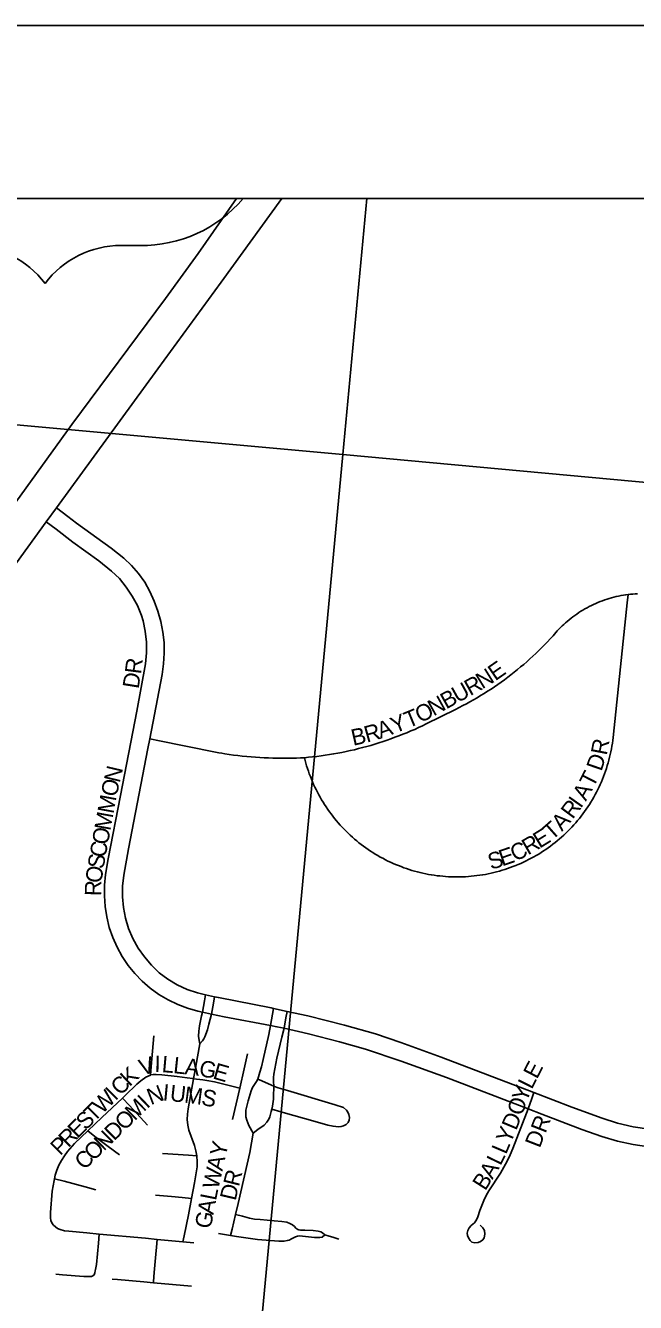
# Model space of a CAD drawing. Extents: x -209 to 4852, y 0 to 905.
# Drawn here: x 110.88 to 117.93, y 325.8 to 340.56 of the extents above; entities that cross this region are included whole.
import ezdxf

# ---------------------------------------------------------------- set-up
doc = ezdxf.new("R2010")
doc.units = 0
for name, color, linetype in [('Default', 7, 'Continuous'), ('GM_X_Airport_Location_Class_2', 7, 'Continuous'), ('GM_X_Airport_Location_Class_3', 7, 'Continuous'), ('GM_X_Interchange_Ramps', 7, 'Continuous'), ('GM_X_Minor_Lake_Text', 7, 'Continuous'), ('GM_X_Minor_River', 7, 'Continuous'), ('GM_X_US_Location', 7, 'Continuous'), ('GM_X_US_Route', 7, 'Continuous'), ('SH_Data', 7, 'Continuous')]:
    doc.layers.add(name, color=color, linetype=linetype)

msp = doc.modelspace()

# ---------------------------------------------------------------- linework, layer by layer
at = {"layer": 'Default'}
for points in [[(59.342, 338.559), (195.342, 338.559), (195.342, 202.559), (59.342, 202.559)], [(195.342, 202.559), (195.342, 338.559), (59.342, 338.559), (59.342, 202.559)]]:
    msp.add_lwpolyline(points, close=True, dxfattribs=at)
at = {"layer": 'GM_X_Airport_Location_Class_2'}
for points in [[(111.234, 334.986), (112.407, 336.59), (113.139, 337.594), (113.838, 338.559)], [(111.116, 334.823), (111.234, 334.986)], [(111.234, 334.986), (111.366, 334.885), (111.465, 334.809), (111.868, 334.518), (112.013, 334.402), (112.102, 334.317), (112.183, 334.225), (112.255, 334.125), (112.314, 334.017), (112.364, 333.904), (112.405, 333.788), (112.44, 333.669), (112.464, 333.549), (112.477, 333.426), (112.479, 333.303), (112.47, 333.18), (112.454, 333.057), (112.312, 332.314)], [(100.635, 320.765), (100.879, 321.1), (101.138, 321.454), (101.471, 321.891), (101.832, 322.33), (102.235, 322.799), (102.722, 323.368), (103.032, 323.752), (103.379, 324.196), (103.741, 324.686), (105.127, 326.6), (106.118, 327.963), (107.027, 329.212), (108.315, 330.965), (109.157, 332.119), (109.921, 333.176), (111.116, 334.823)], [(111.116, 334.823), (111.229, 334.736), (111.422, 334.587), (111.725, 334.37), (111.871, 334.253), (111.961, 334.166), (112.041, 334.069), (112.11, 333.965), (112.17, 333.855), (112.218, 333.739), (112.236, 333.679), (112.261, 333.557), (112.275, 333.432), (112.276, 333.307), (112.264, 333.183), (112.162, 332.633), (111.974, 331.658), (111.831, 330.928), (111.802, 330.745), (111.79, 330.622), (111.788, 330.499), (111.796, 330.376), (111.815, 330.255), (111.845, 330.135), (111.886, 330.019), (111.936, 329.907), (111.995, 329.799), (112.063, 329.696), (112.14, 329.6), (112.225, 329.512), (112.318, 329.431), (112.419, 329.36), (112.525, 329.298), (112.635, 329.244), (112.75, 329.2), (112.869, 329.166), (112.921, 329.155)], [(114.099, 332.096), (114.147, 332.101), (114.194, 332.106), (114.243, 332.111), (114.292, 332.118), (114.34, 332.125), (114.389, 332.132), (114.437, 332.14), (114.485, 332.149), (114.533, 332.158), (114.582, 332.168), (114.63, 332.178), (114.677, 332.189), (114.725, 332.201), (114.772, 332.213), (114.82, 332.226), (114.867, 332.239), (114.914, 332.253), (114.961, 332.268), (115.008, 332.283), (115.054, 332.299), (115.1, 332.315), (115.146, 332.332), (115.192, 332.349), (115.238, 332.367), (115.283, 332.385), (115.329, 332.405), (115.374, 332.424), (115.418, 332.444), (115.463, 332.465), (115.507, 332.486), (115.845, 332.655), (115.887, 332.676), (115.929, 332.698), (115.971, 332.72), (116.013, 332.743), (116.054, 332.766), (116.095, 332.79), (116.136, 332.814), (116.176, 332.839), (116.216, 332.864), (116.256, 332.89), (116.295, 332.916), (116.334, 332.943), (116.373, 332.97), (116.412, 332.998), (116.45, 333.027), (116.487, 333.055), (116.524, 333.085), (116.561, 333.114), (116.598, 333.145), (116.634, 333.175), (116.67, 333.206), (116.705, 333.238), (116.74, 333.27), (116.775, 333.302), (116.809, 333.335), (116.842, 333.369), (116.876, 333.402), (116.909, 333.437), (116.941, 333.471), (116.973, 333.506), (117.005, 333.542), (117.022, 333.561), (117.041, 333.581), (117.059, 333.6), (117.078, 333.619), (117.098, 333.637), (117.118, 333.655), (117.138, 333.672), (117.159, 333.69), (117.181, 333.708), (117.203, 333.725), (117.225, 333.741), (117.248, 333.757), (117.271, 333.773), (117.295, 333.788), (117.318, 333.803), (117.342, 333.817), (117.367, 333.83), (117.391, 333.843), (117.416, 333.856), (117.441, 333.868), (117.467, 333.88), (117.492, 333.891), (117.518, 333.901), (117.544, 333.911), (117.57, 333.92), (117.597, 333.929), (117.623, 333.938), (117.65, 333.945), (117.677, 333.952), (117.704, 333.959), (117.731, 333.965), (117.759, 333.971), (117.786, 333.975), (117.814, 333.98), (117.841, 333.984)], [(114.099, 332.096), (114.107, 332.065), (114.116, 332.034), (114.125, 332.003), (114.135, 331.972), (114.145, 331.941), (114.156, 331.909), (114.168, 331.878), (114.18, 331.848), (114.193, 331.817), (114.206, 331.787), (114.22, 331.757), (114.235, 331.727), (114.25, 331.698), (114.265, 331.668), (114.281, 331.639), (114.298, 331.611), (114.315, 331.583), (114.332, 331.554), (114.35, 331.527), (114.369, 331.499), (114.388, 331.472), (114.408, 331.446), (114.428, 331.42), (114.448, 331.394), (114.469, 331.368), (114.491, 331.343), (114.513, 331.318), (114.535, 331.294), (114.558, 331.27), (114.581, 331.246), (114.605, 331.223), (114.629, 331.2), (114.654, 331.178), (114.678, 331.156), (114.704, 331.135), (114.729, 331.114), (114.755, 331.094), (114.782, 331.074), (114.809, 331.055), (114.836, 331.036), (114.863, 331.017), (114.891, 330.999), (114.919, 330.982), (114.948, 330.965), (114.976, 330.948), (115.005, 330.933), (115.035, 330.917), (115.064, 330.902), (115.094, 330.888), (115.124, 330.874), (115.154, 330.861), (115.185, 330.849), (115.216, 330.837), (115.247, 330.825), (115.278, 330.814), (115.31, 330.804), (115.341, 330.794), (115.373, 330.785), (115.405, 330.776), (115.437, 330.768), (115.469, 330.761), (115.502, 330.754), (115.534, 330.748), (115.567, 330.742), (115.599, 330.737), (115.632, 330.732), (115.665, 330.729), (115.698, 330.725), (115.731, 330.723), (115.764, 330.72), (115.797, 330.719), (115.83, 330.718), (115.863, 330.718), (115.896, 330.718), (115.929, 330.719), (115.962, 330.72), (115.995, 330.723), (116.028, 330.725), (116.061, 330.729), (116.094, 330.733), (116.127, 330.737), (116.159, 330.742), (116.192, 330.748), (116.224, 330.754), (116.257, 330.761), (116.289, 330.769), (116.321, 330.777), (116.353, 330.785), (116.385, 330.795), (116.416, 330.804), (116.448, 330.815), (116.479, 330.826), (116.51, 330.837), (116.541, 330.849), (116.552, 330.854), (116.571, 330.862), (116.602, 330.875), (116.632, 330.889), (116.662, 330.903), (116.691, 330.918), (116.721, 330.933), (116.75, 330.949), (116.778, 330.966), (116.807, 330.983), (116.835, 331), (116.863, 331.018), (116.89, 331.036), (116.917, 331.055), (116.944, 331.075), (116.97, 331.095), (116.996, 331.115), (117.022, 331.136), (117.047, 331.157), (117.072, 331.179), (117.097, 331.201), (117.121, 331.224), (117.144, 331.247), (117.168, 331.271), (117.19, 331.295), (117.213, 331.319), (117.235, 331.344), (117.256, 331.369), (117.277, 331.395), (117.298, 331.421), (117.318, 331.447), (117.337, 331.474), (117.356, 331.501), (117.375, 331.528), (117.393, 331.556), (117.411, 331.584), (117.428, 331.612), (117.444, 331.641), (117.46, 331.67), (117.476, 331.699), (117.491, 331.728), (117.505, 331.758), (117.519, 331.788), (117.532, 331.819), (117.545, 331.849), (117.557, 331.88), (117.569, 331.911), (117.58, 331.942), (117.59, 331.973), (117.6, 332.005), (117.61, 332.037), (117.618, 332.068), (117.627, 332.101), (117.634, 332.133), (117.641, 332.165), (117.648, 332.197), (117.654, 332.23), (117.659, 332.263), (117.663, 332.296), (117.668, 332.328), (117.804, 333.628), (117.831, 333.887), (117.841, 333.984)], [(117.841, 333.984), (117.868, 333.986), (117.894, 333.988), (117.921, 333.99), (117.948, 333.99)], [(112.312, 332.314), (112.291, 332.203), (112.066, 331.044), (112.011, 330.738), (111.998, 330.613), (111.996, 330.488), (112.007, 330.363), (112.03, 330.24), (112.067, 330.12), (112.116, 330.005), (112.178, 329.896), (112.25, 329.793), (112.331, 329.697), (112.422, 329.611), (112.523, 329.536), (112.63, 329.472), (112.744, 329.418), (112.863, 329.378), (112.958, 329.356)], [(112.312, 332.314), (112.333, 332.31), (112.404, 332.295), (113.073, 332.159), (113.109, 332.153), (113.145, 332.147), (113.181, 332.141), (113.231, 332.134), (113.281, 332.127), (113.332, 332.121), (113.382, 332.115), (113.433, 332.11), (113.483, 332.105), (113.534, 332.101), (113.584, 332.098), (113.635, 332.095), (113.686, 332.093), (113.736, 332.091), (113.787, 332.09), (113.832, 332.089), (113.876, 332.089), (113.921, 332.09), (113.965, 332.091), (114.01, 332.092), (114.054, 332.094), (114.099, 332.096)], [(112.921, 329.155), (112.945, 329.287), (112.958, 329.356)], [(112.958, 329.356), (113.062, 329.333)], [(113.024, 329.133), (113.048, 329.258), (113.062, 329.333)], [(113.062, 329.333), (113.106, 329.323), (113.715, 329.203), (113.741, 329.198)], [(112.89, 328.79), (112.882, 328.826), (112.875, 328.876), (112.879, 328.937), (112.886, 328.998), (112.909, 329.112), (112.921, 329.155)], [(112.921, 329.155), (113.024, 329.133)], [(113.708, 329.001), (113.731, 329.133), (113.741, 329.198)], [(113.741, 329.198), (113.899, 329.164)], [(113.899, 329.164), (113.886, 329.088), (113.865, 328.968)], [(113.899, 329.164), (114.14, 329.112), (114.562, 329.006), (114.92, 328.904), (115.214, 328.805), (115.68, 328.634), (116.751, 328.225)], [(112.89, 328.79), (112.923, 328.825), (112.936, 328.846), (112.949, 328.871), (112.979, 328.952), (112.995, 329.018), (113.024, 329.133)], [(113.024, 329.133), (113.171, 329.101), (113.708, 329.001)], [(113.56, 328.38), (113.57, 328.408), (113.586, 328.46), (113.605, 328.524), (113.622, 328.608), (113.687, 328.896), (113.708, 329.001)], [(113.708, 329.001), (113.781, 328.987), (113.865, 328.968)], [(112.321, 328.428), (112.33, 328.525), (112.36, 328.88)], [(113.865, 328.968), (113.84, 328.864), (113.782, 328.622), (113.745, 328.437), (113.741, 328.398), (113.742, 328.353), (113.746, 328.298)], [(113.865, 328.968), (114.145, 328.906), (114.506, 328.812), (114.804, 328.726), (115.216, 328.59), (115.741, 328.398), (116.684, 328.038)], [(112.819, 328.386), (112.845, 328.529), (112.89, 328.79)], [(113.353, 328.277), (113.404, 328.498), (113.44, 328.674)], [(111.998, 328.161), (112.029, 328.19), (112.161, 328.321), (112.209, 328.361), (112.265, 328.403), (112.293, 328.416), (112.321, 328.428)], [(112.321, 328.428), (112.326, 328.43), (112.354, 328.435), (112.388, 328.436), (112.452, 328.432), (112.63, 328.41), (112.743, 328.395), (112.81, 328.387), (112.819, 328.386)], [(112.856, 327.495), (112.845, 327.553), (112.829, 327.613), (112.764, 327.789), (112.751, 327.85), (112.745, 327.913), (112.747, 327.975), (112.755, 328.037), (112.819, 328.386)], [(112.819, 328.386), (112.924, 328.373), (112.97, 328.365), (113.061, 328.348), (113.321, 328.284), (113.353, 328.277)], [(113.27, 327.915), (113.353, 328.277)], [(113.509, 327.755), (113.458, 327.846), (113.434, 327.905), (113.423, 327.944), (113.421, 327.981), (113.424, 328.022), (113.435, 328.07), (113.45, 328.129), (113.484, 328.247), (113.5, 328.285), (113.522, 328.318), (113.544, 328.353), (113.56, 328.38)], [(113.746, 328.298), (113.579, 328.371), (113.56, 328.38)], [(113.746, 328.298), (113.745, 328.272), (113.744, 328.204), (113.741, 328.148), (113.731, 328.067), (113.723, 328.033)], [(113.723, 328.033), (113.827, 328.003), (114.249, 327.884), (114.369, 327.849), (114.431, 327.836), (114.493, 327.831), (114.524, 327.835), (114.552, 327.841), (114.583, 327.857), (114.604, 327.879), (114.617, 327.907), (114.619, 327.938), (114.614, 327.971), (114.603, 327.999), (114.585, 328.024), (114.55, 328.052), (114.455, 328.084), (113.904, 328.249), (113.797, 328.279), (113.753, 328.295), (113.746, 328.298)], [(111.597, 327.782), (111.757, 327.936), (111.998, 328.161)], [(111.998, 328.161), (112.078, 328.077), (112.288, 327.85)], [(116.684, 328.038), (116.727, 328.158), (116.751, 328.225)], [(116.751, 328.225), (117.189, 328.058), (117.539, 327.928), (117.717, 327.872), (117.9, 327.831), (118.085, 327.804), (118.272, 327.79), (118.459, 327.789), (118.645, 327.802), (118.769, 327.82), (118.892, 327.846), (118.952, 327.864), (119.01, 327.887), (119.05, 327.908), (119.087, 327.932), (119.11, 327.946), (119.129, 327.954)], [(113.723, 328.033), (113.717, 328.007), (113.699, 327.946), (113.687, 327.919), (113.664, 327.882), (113.633, 327.849), (113.562, 327.797), (113.509, 327.755)], [(116.131, 326.691), (116.16, 326.663), (116.18, 326.632), (116.186, 326.589), (116.176, 326.548), (116.16, 326.524), (116.135, 326.503), (116.106, 326.491), (116.07, 326.487), (116.035, 326.497), (116.014, 326.517), (115.994, 326.546), (115.984, 326.573), (115.982, 326.601), (115.988, 326.632), (116.004, 326.663), (116.027, 326.689), (116.064, 326.72), (116.088, 326.753), (116.104, 326.788), (116.127, 326.861), (116.173, 326.978), (116.2, 327.035), (116.231, 327.089), (116.364, 327.295), (116.424, 327.399), (116.453, 327.456), (116.477, 327.506), (116.507, 327.579), (116.665, 327.988), (116.684, 328.038)], [(116.684, 328.038), (116.842, 327.977), (117.305, 327.8), (117.538, 327.716), (117.716, 327.664), (117.897, 327.626), (118.08, 327.6), (118.265, 327.587), (118.45, 327.59), (118.634, 327.608), (118.94, 327.662), (119.007, 327.671), (119.073, 327.676), (119.133, 327.677), (119.167, 327.679), (119.189, 327.681), (119.206, 327.684)], [(111.211, 327.23), (111.22, 327.269), (111.239, 327.328), (111.263, 327.385), (111.292, 327.44), (111.325, 327.493), (111.362, 327.543), (111.444, 327.636), (111.597, 327.782)], [(111.597, 327.782), (111.677, 327.719), (111.83, 327.601), (111.961, 327.507)], [(113.304, 326.818), (113.333, 326.942), (113.469, 327.531), (113.509, 327.755)], [(112.461, 327.521), (112.759, 327.502), (112.856, 327.495)], [(112.796, 327.002), (112.831, 327.181), (112.86, 327.367), (112.862, 327.429), (112.857, 327.491), (112.856, 327.495)], [(111.727, 326.59), (111.585, 326.603), (111.378, 326.623), (111.326, 326.628), (111.278, 326.642), (111.247, 326.656), (111.224, 326.672), (111.201, 326.692), (111.183, 326.714), (111.17, 326.747), (111.166, 326.777), (111.164, 326.839), (111.186, 327.086), (111.206, 327.209), (111.211, 327.23)], [(111.211, 327.23), (111.322, 327.2), (111.567, 327.134), (111.689, 327.101)], [(112.377, 327.04), (112.564, 327.026), (112.688, 327.013), (112.796, 327.002)], [(112.694, 326.501), (112.708, 326.568), (112.759, 326.813), (112.796, 327.002)], [(113.246, 326.572), (113.264, 326.647), (113.304, 326.818)], [(113.304, 326.818), (113.385, 326.795), (113.465, 326.775), (113.523, 326.763), (113.587, 326.758), (113.751, 326.744), (113.84, 326.734), (113.896, 326.726), (113.932, 326.713), (113.963, 326.698), (113.984, 326.677), (114.002, 326.657), (114.023, 326.644), (114.036, 326.64), (114.054, 326.636), (114.106, 326.636), (114.199, 326.63), (114.26, 326.623), (114.288, 326.617), (114.307, 326.606), (114.334, 326.58)], [(111.228, 326.125), (111.305, 326.119), (111.551, 326.1), (111.609, 326.099), (111.637, 326.101), (111.654, 326.107), (111.668, 326.12), (111.676, 326.141), (111.682, 326.165), (111.685, 326.179), (111.695, 326.24), (111.718, 326.483), (111.727, 326.59)], [(112.398, 326.528), (112.264, 326.541), (111.727, 326.59)], [(112.356, 326.027), (112.357, 326.043), (112.363, 326.146), (112.381, 326.356), (112.391, 326.437), (112.398, 326.528)], [(112.694, 326.501), (112.398, 326.528)], [(112.82, 326.49), (112.694, 326.501)], [(113.107, 326.598), (113.246, 326.572)], [(113.246, 326.572), (113.315, 326.56), (113.558, 326.528), (113.805, 326.508), (113.866, 326.508), (113.901, 326.514), (113.924, 326.521), (113.952, 326.535), (113.996, 326.558), (114.018, 326.567), (114.042, 326.569), (114.216, 326.55), (114.245, 326.549), (114.276, 326.549), (114.304, 326.556), (114.334, 326.58)], [(114.334, 326.58), (114.384, 326.565), (114.427, 326.553), (114.464, 326.542), (114.496, 326.531)], [(111.879, 326.07), (111.939, 326.064), (112.242, 326.038), (112.356, 326.027)], [(112.356, 326.027), (112.795, 325.986)]]:
    msp.add_lwpolyline(points, dxfattribs=at)
at = {"layer": 'GM_X_Interchange_Ramps'}
for p, q in [((113.39, 338.559), (108.813, 338.559)), ((111.981, 338.016), (112.2, 338.016))]:
    msp.add_line(p, q, dxfattribs=at)
for centre, radius, start, end in [((112.218, 339.554), 1.538, 269.3617, 319.6872), ((110.223, 336.918), 1.099, 36.8699, 90), ((111.981, 336.918), 1.099, 90, 143.1301)]:
    msp.add_arc(centre, radius, start, end, dxfattribs=at)
at = {"layer": 'GM_X_Minor_Lake_Text'}
msp.add_lwpolyline([(195.342, 338.559), (102.839, 338.559), (102.868, 338.282), (102.892, 337.606), (102.59, 336.588), (102.785, 335.735), (102.479, 335.255), (101.683, 335.242), (101.365, 334.52), (100.745, 334.207), (101.101, 332.393), (100.044, 332.219)], dxfattribs=at)
at = {"layer": 'GM_X_Minor_River'}
for points in [[(114.819, 338.559), (94.444, 338.559), (94.333, 337.437), (114.544, 335.599)], [(134.994, 338.559), (114.819, 338.559), (114.544, 335.599), (134.543, 333.757)], [(94.333, 337.437), (114.544, 335.599), (112.672, 315.623), (92.468, 317.445)], [(114.544, 335.599), (134.543, 333.757), (132.725, 313.81), (112.672, 315.623)]]:
    msp.add_lwpolyline(points, close=True, dxfattribs=at)
at = {"layer": 'GM_X_US_Location'}
msp.add_lwpolyline([(125.622, 338.559), (98.504, 338.559)], dxfattribs=at)
at = {"layer": 'GM_X_US_Route'}
msp.add_lwpolyline([(78.655, 290.839), (80.362, 293.189), (81.429, 294.658), (81.54, 294.81), (83.329, 297.271), (86.164, 301.171), (87.313, 302.756), (87.726, 303.323), (87.969, 303.658), (88.207, 303.986), (91.74, 308.847), (94.398, 312.5), (100.465, 320.845), (100.676, 321.133), (101.601, 322.421), (102.107, 323.11), (107.543, 330.594), (107.902, 331.087), (111.413, 335.948), (112.494, 337.404), (112.873, 337.925), (113.316, 338.559)], dxfattribs=at)
at = {"layer": 'SH_Data'}
msp.add_line((57.342, 340.559), (197.342, 340.559), dxfattribs=at)

# ---------------------------------------------------------------- texts
at = {"layer": 'GM_X_Airport_Location_Class_3'}
for s, height, rotation, p in [('R', 0.189, 82.5789, (112.21, 333.056)), ('N', 0.189, 31.7722, (116.155, 332.884)), ('E', 0.189, 34.7411, (116.305, 332.978)), ('D', 0.189, 80.9581, (112.183, 332.886)), ('R', 0.189, 28.998, (116.015, 332.806)), ('B', 0.189, 28.9976, (115.738, 332.653)), ('U', 0.189, 28.9994, (115.869, 332.725)), ('O', 0.189, 27.1994, (115.438, 332.493)), ('N', 0.189, 28.9797, (115.592, 332.572)), ('Y', 0.189, 21.5792, (115.141, 332.373)), ('T', 0.189, 22.294, (115.299, 332.435)), ('B', 0.189, 12.6579, (114.663, 332.233)), ('R', 0.189, 15.747, (114.82, 332.269)), ('A', 0.189, 19.8023, (114.978, 332.314)), ('R', 0.189, 79.1863, (117.593, 332.117)), ('D', 0.189, 71.0232, (117.531, 331.931)), ('N', 0.189, 76.6581, (111.964, 331.798)), ('T', 0.189, 62.7966, (117.438, 331.74)), ('O', 0.189, 77.4854, (111.928, 331.636)), ('M', 0.189, 79.4866, (111.892, 331.441)), ('A', 0.189, 60.4592, (117.352, 331.587)), ('R', 0.189, 53.4353, (117.2, 331.377)), ('I', 0.189, 54.7646, (117.293, 331.502)), ('M', 0.189, 79.6723, (111.856, 331.245)), ('T', 0.189, 41.4838, (116.959, 331.134)), ('A', 0.189, 47.5657, (117.075, 331.238)), ('O', 0.189, 79.6812, (111.827, 331.081)), ('E', 0.189, 31.6038, (116.817, 331.043)), ('C', 0.189, 79.6712, (111.8, 330.933)), ('E', 0.189, 18.6248, (116.384, 330.839)), ('C', 0.189, 26.0346, (116.535, 330.892)), ('R', 0.189, 30.326, (116.683, 330.965)), ('S', 0.189, 79.81, (111.776, 330.802)), ('S', 0.189, 18.5732, (116.257, 330.797)), ('O', 0.189, 81.8637, (111.753, 330.639)), ('R', 0.189, 88.5673, (111.75, 330.495)), ('V', 0.189, 16.8311, (112.222, 328.418)), ('I', 0.189, 359.3445, (112.366, 328.464)), ('L', 0.189, 354.9936, (112.446, 328.463)), ('L', 0.189, 353.9796, (112.578, 328.451)), ('A', 0.189, 353.5391, (112.71, 328.437)), ('G', 0.189, 349.4703, (112.872, 328.419)), ('E', 0.189, 344.0884, (113.031, 328.39)), ('E', 0.189, 62.6041, (116.787, 328.373)), ('C', 0.189, 44.9045, (111.973, 328.182)), ('K', 0.189, 43.0368, (112.078, 328.287)), ('W', 0.189, 44.9024, (111.761, 327.97)), ('I', 0.189, 44.8764, (111.914, 328.123)), ('N', 0.189, 21.083, (112.324, 328.079)), ('I', 0.189, 354.5721, (112.457, 328.136)), ('U', 0.189, 353.8457, (112.539, 328.128)), ('M', 0.189, 352.4005, (112.704, 328.111)), ('S', 0.189, 348.9741, (112.899, 328.085)), ('Y', 0.189, 67.9266, (116.666, 328.104)), ('L', 0.189, 63.1783, (116.727, 328.254)), ('T', 0.189, 44.8841, (111.666, 327.876)), ('M', 0.189, 44.2529, (112.138, 327.893)), ('I', 0.189, 43.6405, (112.281, 328.032)), ('O', 0.189, 71.9063, (116.616, 327.949)), ('S', 0.189, 44.9053, (111.572, 327.782)), ('O', 0.189, 44.3972, (112.019, 327.777)), ('D', 0.189, 67.299, (116.546, 327.779)), ('E', 0.189, 44.9053, (111.477, 327.688)), ('D', 0.189, 44.4258, (111.9, 327.66)), ('Y', 0.189, 67.2489, (116.481, 327.625)), ('DR', 0.1894, 68.7471, (116.819, 327.576)), ('P', 0.189, 44.8841, (111.277, 327.488)), ('R', 0.189, 44.9045, (111.371, 327.582)), ('N', 0.189, 44.4099, (111.781, 327.543)), ('Y', 0.189, 77.3174, (113.188, 327.474)), ('C', 0.189, 44.4161, (111.555, 327.322)), ('O', 0.189, 44.4099, (111.662, 327.427)), ('L', 0.189, 66.9846, (116.429, 327.502)), ('W', 0.189, 77.3217, (113.104, 327.1)), ('A', 0.189, 77.3174, (113.151, 327.311)), ('A', 0.189, 59.1143, (116.272, 327.214)), ('L', 0.189, 63.9986, (116.366, 327.372)), ('R', 0.189, 75.9696, (113.342, 327.13)), ('B', 0.189, 57.6033, (116.189, 327.082)), ('L', 0.189, 78.8669, (113.078, 326.97)), ('D', 0.189, 76.812, (113.304, 326.968)), ('A', 0.189, 79.2044, (113.047, 326.807)), ('G', 0.189, 79.2044, (113.016, 326.643))]:
    msp.add_text(s, height=height, rotation=rotation, dxfattribs=at).set_placement(p)

doc.saveas('drawing.dxf')
